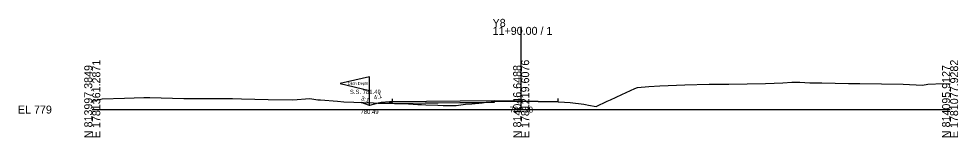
# Model space of a CAD drawing. Extents: x -26 to 303, y -10 to 5036.
# Drawn here: x -25.7 to 302.8, y 2990.3 to 3031.8 of the extents above; entities that cross this region are included whole.
import ezdxf

# ---------------------------------------------------------------- set-up
doc = ezdxf.new("R2010")
doc.units = 0
for name, color, linetype in [('Exist Cross Section Cell', 7, 'Continuous'), ('Exist XS Center Line Elevation Label', 7, 'Continuous'), ('Exist XS Ground Line', 7, 'Continuous'), ('Prop XS Ditch Slope Text', 7, 'Continuous'), ('Prop XS Ditch Standard Text', 7, 'Continuous'), ('Prop XS Dump Level', 7, 'Continuous'), ('Prop XS Earthwork Shape', 7, 'Continuous'), ('Prop XS EOT Tick Mark', 7, 'Continuous'), ('Prop XS Finish Grade', 7, 'Continuous'), ('Prop XS Finish Grade Earthwork', 7, 'Continuous'), ('Prop XS Finish Grade Pavement', 7, 'Continuous'), ('Prop XS Pvmt Edge Slope', 7, 'Continuous'), ('Prop XS Side Slope Text', 7, 'Continuous'), ('Prop XS SS Elevation Text', 7, 'Continuous'), ('Prop XS Subgrade Earthwork', 7, 'Continuous')]:
    doc.layers.add(name, color=color, linetype=linetype)

msp = doc.modelspace()

# ---------------------------------------------------------------- linework, layer by layer
at = {"layer": 'Exist Cross Section Cell'}
for p, q in [((150, 3000), (150, 3028.99)), ((0, 3000), (150, 3000)), ((150, 3000), (300, 3000))]:
    msp.add_line(p, q, dxfattribs=at)
at = {"layer": 'Exist XS Ground Line'}
for p, q in [((241.52, 3009.33), (244.6, 3009.58)), ((244.6, 3009.58), (246.31, 3009.66)), ((246.31, 3009.66), (247.5, 3009.64)), ((247.5, 3009.64), (250.98, 3009.41)), ((250.98, 3009.41), (255.1, 3009.32)), ((185.17, 3005.24), (189.76, 3007.36)), ((189.76, 3007.36), (190.72, 3007.79)), ((190.72, 3007.79), (194.66, 3008.11)), ((194.66, 3008.11), (198.52, 3008.27)), ((198.52, 3008.27), (207.21, 3008.7)), ((207.21, 3008.7), (215.71, 3008.89)), ((215.71, 3008.89), (222.59, 3008.96)), ((222.59, 3008.96), (235.42, 3009.13)), ((235.42, 3009.13), (241.52, 3009.33)), ((255.1, 3009.32), (264.45, 3009.2)), ((264.45, 3009.2), (268.42, 3009.16)), ((268.42, 3009.16), (283.56, 3008.89)), ((283.56, 3008.89), (290.34, 3008.58)), ((290.34, 3008.58), (292.27, 3008.9)), ((292.27, 3008.9), (297.66, 3009.11)), ((297.66, 3009.11), (300, 3009)), ((0, 3002.96), (1.07, 3003.13)), ((1.07, 3003.13), (3.52, 3003.76)), ((3.52, 3003.76), (11.28, 3003.99)), ((11.28, 3003.99), (18.07, 3004.29)), ((18.07, 3004.29), (20.12, 3004.22)), ((20.12, 3004.22), (32.01, 3003.83)), ((32.01, 3003.83), (33.89, 3003.86)), ((33.89, 3003.86), (36.17, 3003.88)), ((36.17, 3003.88), (38.6, 3003.91)), ((38.6, 3003.91), (49.1, 3003.88)), ((49.1, 3003.88), (52.2, 3003.77)), ((52.2, 3003.77), (61.55, 3003.56)), ((61.55, 3003.56), (70.17, 3003.39)), ((70.17, 3003.39), (76.08, 3003.9)), ((76.08, 3003.9), (78.88, 3003.45)), ((78.88, 3003.45), (79.87, 3003.37)), ((79.87, 3003.37), (85.71, 3002.9)), ((85.71, 3002.9), (87.94, 3002.69)), ((139.54, 3002.74), (139.96, 3002.8)), ((139.96, 3002.8), (140.43, 3002.91)), ((140.43, 3002.91), (146.02, 3002.95)), ((146.02, 3002.95), (150, 3002.98)), ((150, 3002.98), (150.62, 3002.99)), ((150.62, 3002.99), (155.9, 3002.87)), ((155.9, 3002.87), (162.94, 3002.73)), ((176.19, 3001.04), (180.03, 3002.9)), ((180.03, 3002.9), (180.67, 3003.19)), ((180.67, 3003.19), (181.25, 3003.47)), ((181.25, 3003.47), (185.17, 3005.24)), ((87.94, 3002.69), (98.41, 3002.35)), ((98.41, 3002.35), (100.02, 3002.25)), ((100.02, 3002.25), (104.05, 3002.21)), ((104.05, 3002.21), (108.96, 3002.13)), ((108.96, 3002.13), (113.87, 3001.8)), ((113.87, 3001.8), (115.09, 3001.76)), ((115.09, 3001.76), (116.66, 3001.69)), ((116.66, 3001.69), (120.89, 3001.53)), ((120.89, 3001.53), (122.75, 3001.48)), ((122.75, 3001.48), (127.22, 3001.49)), ((127.22, 3001.49), (130.51, 3001.89)), ((130.51, 3001.89), (132.71, 3002.06)), ((132.71, 3002.06), (137.79, 3002.57)), ((137.79, 3002.57), (139.54, 3002.74)), ((162.94, 3002.73), (165.14, 3002.59)), ((165.14, 3002.59), (167.12, 3002.44)), ((167.12, 3002.44), (171.95, 3001.88)), ((171.95, 3001.88), (172.48, 3001.8)), ((172.48, 3001.8), (173.52, 3001.6)), ((173.52, 3001.6), (176.19, 3001.04))]:
    msp.add_line(p, q, dxfattribs=at)
at = {"layer": 'Prop XS Dump Level'}
for p, q in [((97, 3011.49), (86.7, 3009.09)), ((97, 3006.69), (97, 3011.49)), ((86.7, 3009.09), (97, 3006.69)), ((97, 3001.49), (97, 3006.69))]:
    msp.add_line(p, q, dxfattribs=at)
at = {"layer": 'Prop XS Earthwork Shape'}
for points in [[(136.34, 3002.42), (137.79, 3002.57), (139.54, 3002.74), (139.96, 3002.8), (140.43, 3002.91), (140.51, 3002.91), (140.51, 3002.45)], [(94.01, 3002.49), (98.41, 3002.35), (100.02, 3002.25), (100.04, 3002.25), (97, 3001.49)], [(104.38, 3002.21), (103.9, 3002.69), (101, 3002.49), (100.04, 3002.25), (104.05, 3002.21)], [(105.68, 3002.19), (104.41, 3002.18), (104.38, 3002.21)], [(136.34, 3002.42), (105.68, 3002.19), (108.96, 3002.13), (113.87, 3001.8), (115.09, 3001.76), (116.66, 3001.69), (120.89, 3001.53), (122.75, 3001.48), (127.22, 3001.49), (130.51, 3001.89), (132.71, 3002.06)]]:
    msp.add_lwpolyline(points, close=True, dxfattribs=at)
at = {"layer": 'Prop XS EOT Tick Mark'}
for p, q in [((105, 3002.76), (105, 3003.76)), ((162.94, 3002.86), (162.94, 3003.86))]:
    msp.add_line(p, q, dxfattribs=at)
at = {"layer": 'Prop XS Finish Grade'}
msp.add_line((105, 3002.76), (103.9, 3002.69), dxfattribs=at)
at = {"layer": 'Prop XS Finish Grade Earthwork'}
for p, q in [((97, 3001.49), (94.01, 3002.49)), ((101, 3002.49), (97, 3001.49)), ((103.9, 3002.69), (101, 3002.49))]:
    msp.add_line(p, q, dxfattribs=at)
at = {"layer": 'Prop XS Finish Grade Pavement'}
for p, q in [((140.51, 3003.04), (105, 3002.76)), ((140.43, 3003.04), (146.02, 3003.08)), ((140.51, 3003.04), (140.52, 3002.91)), ((146.02, 3003.08), (150, 3003.11)), ((150, 3003.11), (150.62, 3003.11)), ((150.63, 3003.11), (155.9, 3003)), ((155.9, 3003), (162.94, 3002.86))]:
    msp.add_line(p, q, dxfattribs=at)
at = {"layer": 'Prop XS Pvmt Edge Slope'}
msp.add_line((105, 3002.76), (104.41, 3002.18), dxfattribs=at)
at = {"layer": 'Prop XS Subgrade Earthwork'}
for p, q in [((140.51, 3002.45), (140.51, 3002.91)), ((104.41, 3002.18), (103.9, 3002.69)), ((140.51, 3002.45), (104.41, 3002.18))]:
    msp.add_line(p, q, dxfattribs=at)

# ---------------------------------------------------------------- texts
at = {"layer": 'Exist Cross Section Cell'}
for s, p in [('Y8', (140, 3028.99)), ('11+90.00 / 1', (140, 3026.19)), ('EL 779', (-26, 2998.6))]:
    msp.add_text(s, height=2.8, dxfattribs=at).set_placement(p)
for s, p in [('E 1781361.2871', (2.8, 2990)), ('E 1781219.6076', (152.8, 2990)), ('E 1781077.9282', (302.8, 2990)), ('N 813997.3849', (0, 2990)), ('N 814046.6488', (150, 2990)), ('N 814095.9127', (300, 2990))]:
    msp.add_text(s, height=2.8, rotation=90, dxfattribs=at).set_placement(p)
at = {"layer": 'Exist XS Center Line Elevation Label'}
msp.add_text('781.98', height=2, dxfattribs=at).set_placement((145.96, 2998.98))
at = {"layer": 'Prop XS Ditch Slope Text'}
msp.add_text('4:1', height=1.5, rotation=14.0362, dxfattribs=at).set_placement((98.64, 3003.45))
at = {"layer": 'Prop XS Ditch Standard Text'}
msp.add_text('780.49', height=1.5, dxfattribs=at).set_placement((93.8, 2998.49))
at = {"layer": 'Prop XS Dump Level'}
for s, height, p in [('Ditch Depth', 1, (89.34, 3008.66)), ('Eop', 0.3, (140.51, 3002.61)), ('Case1', 0.04, (101, 3002.45))]:
    msp.add_text(s, height=height, dxfattribs=at).set_placement(p)
at = {"layer": 'Prop XS Side Slope Text'}
msp.add_text('3:1', height=1.5, rotation=341.5651, dxfattribs=at).set_placement((93.83, 3003.35))
at = {"layer": 'Prop XS SS Elevation Text'}
msp.add_text('S.S. 781.49', height=1.5, dxfattribs=at).set_placement((90.09, 3005.46))

doc.saveas('drawing.dxf')
